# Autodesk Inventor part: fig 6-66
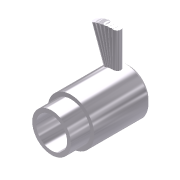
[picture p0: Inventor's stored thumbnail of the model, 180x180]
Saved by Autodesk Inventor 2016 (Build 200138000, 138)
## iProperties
Shininess: 77.0
Angle Display Precision: 2
Document Length Units: 11269
Document Angle Units: 11279
Document Time Units: 11290
Document Mass Units: 11283
Document Length Units Precision: 3
Document Angle Units Precision: 2
Compacted: True
Created: 2001-12
Part Number: fig 6-66
Document SubType Name: Modeling
Designer: Renu Muthoo
Density: 1 g/cm^3
Material: Generic
Appearance: Metal-AL-6061 (Polished)
Density: 0.0
Volumn: 0.0
Area: 0.0
PropertySet Name: Model Information
Control State: 0
Master: False
Checked Out: False
Author: Renu Muthoo
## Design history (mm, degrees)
sketch "Sketch2"
  geometry: L1 (-9.573, -4.327)-(-9.573, -5.327); L2 (-9.573, -5.327)-(-4.573, -5.327); L3 (-4.573, -5.327)-(-4.573, -6.327); L4 (-4.573, -6.327)-(9.427, -6.327); L5 (9.427, -6.327)-(10.427, -5.327); L6 (10.427, -5.327)-(10.427, -4.327); L7 (10.427, -4.327)-(-9.573, -4.327); L8 (-13.687, -0.327)-(14, -0.327)
  constraints: 16 end point, 5 parallel, 1 perpendicular, 1 vertical
  dimensions: "d9" = 20 distance of L6.end L1.start; "d10" = 5 distance of L1.end L2.end; "d11" = 12 diameter of L4 L8; "d12" = 10 diameter of L2 L8; "d13" = 8 diameter of L7 L8; "d14" = 45 deg angle of L5 L4; "d15" = 1 horizontal distance of L5.end L4.end
revolve "Revolution2" sketch "Sketch2" stored, may be unused: angle "d16" = 90 deg
workplane "Work Plane1"
workplane "Work Plane2"
sketch "Sketch3"
  geometry: L1 (-4, 8)-(4, 8) reference; C1 r 1 at (-0.098, 5)
  constraints: 1 centre point
  dimensions: "d18" = 3 distance from line of L1 C1.centre; "d19" = 2 diameter of C1
extrude "Extrusion1" join sketch "Sketch3" distance "d20" = 10; taper "d21" = 0 deg
pattern_circular "Circular Pattern3" dims angle "d29" = 20 deg
body "Solid1"
other parameters: "d17" = -1
